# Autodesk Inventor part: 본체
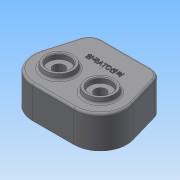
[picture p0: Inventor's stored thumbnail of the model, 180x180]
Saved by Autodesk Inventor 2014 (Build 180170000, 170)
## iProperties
Created: 2014-12
Part Number: 본체
Material: 일반
Document SubType Name: Modeling
Designer: user
Density: 1 g/cm^3
Appearance: 기본값
Author: user
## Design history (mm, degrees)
sketch "스케치1"
  geometry: L1 (-47, 36)-(47, 36); L2 (47, 36)-(62.752, -18.127); L3 (28.186, -64.186)-(-28.186, -64.186); L4 (-62.752, -18.127)-(-47, 36); L5 (-28.186, -28.186)-(0, 0); L6 (0, 0)-(28.186, -28.186); C1 r 46 at (0, 0); A1 r 36 centre (28.186, -28.186) between (28.186, -64.186) and (62.752, -18.127); A2 r 36 centre (-28.186, -28.186) between (-62.752, -18.127) and (-28.186, -64.186); 3 further points
  constraints: 12 end point, 4 point on circle, 4 tangent, 3 centre point, 2 midpoint, 2 vertical alignment, 1 coincident, 1 equal length, 1 equal radius, 1 horizontal, 1 parallel
  dimensions: "d6" = 94 distance of L1.start L1.end; "d7" = 36 radius of A2; "d10" = 36 distance from line of L1 point (0, 0); "d11" = 92 diameter of C1; "d42" = 90 deg angle of L6 L5
extrude "돌출1" new body sketch "스케치1" distance "d12" = 44; taper "d13" = 0 deg
fillet "모깎기1" dims "d14" = 18
sketch "스케치2"
  geometry: C1 r 20 at (-28.186, -28.186); C2 r 20 at (28.186, -28.186); 3 further points
  constraints: 2 centre point, 2 coincident, 1 equal radius
  dimensions: "d15" = 40 diameter of C1
extrude "돌출2" join sketch "스케치2" distance "d16" = 7; taper "d17" = -10 deg
sketch "스케치3"
  geometry: C1 r 18.766 at (0, 0) reference; C2 r 18.766 at (56.372, 0) reference; 3 further points
  constraints: 2 coincident
hole "구멍1" sketch "스케치3" at (0, 0), (56.372, 0) diameter "d18" = 30; stored, may be unused: countersink angle "d22" = 90 deg, drill point angle "d24" = 0 deg; dims "d19" = 6, "d20" = 4, "d21" = 2, "d23" = 7
sketch "스케치4"
  geometry: L1 (-50.775, 23.03)-(-62.752, -18.127) reference; L2 (-28.186, -64.186)-(28.186, -64.186) reference; L3 (62.752, -18.127)-(50.775, 23.03) reference; L4 (33.492, 36)-(-33.492, 36) reference; L5 (33.492, 31)-(-33.492, 31); L6 (-45.974, 21.633)-(-47.997, 14.681); L7 (-52.468, -0.681)-(-57.951, -19.524); L8 (57.951, -19.524)-(52.468, -0.681); L9 (47.997, 14.681)-(45.974, 21.633); L10 (-28.186, -59.186)-(-8, -59.186); L11 (8, -59.186)-(28.186, -59.186); A1 r 18 centre (-33.492, 18) between (-33.492, 36) and (-50.775, 23.03) reference; A2 r 36 centre (-28.186, -28.186) between (-62.752, -18.127) and (-28.186, -64.186) reference; A3 r 36 centre (28.186, -28.186) between (28.186, -64.186) and (62.752, -18.127) reference; A4 r 18 centre (33.492, 18) between (50.775, 23.03) and (33.492, 36) reference; A5 r 13 centre (-33.492, 18) between (-33.492, 31) and (-45.974, 21.633); A6 r 31 centre (-28.186, -28.186) between (-57.951, -19.524) and (-28.186, -59.186); A7 r 31 centre (28.186, -28.186) between (28.186, -59.186) and (57.951, -19.524); A8 r 13 centre (33.492, 18) between (45.974, 21.633) and (33.492, 31); A9 r 8 centre (-50.232, 7) between (-52.468, -0.681) and (-47.997, 14.681); A10 r 8 centre (50.232, 7) between (47.997, 14.681) and (52.468, -0.681); A11 r 8 centre (0, -59.186) between (8, -59.186) and (-8, -59.186); 1 further point
  constraints: 14 end point, 14 point on circle, 7 centre point, 2 equal radius, 1 horizontal alignment, 1 vertical alignment, 1 other
  dimensions: "d25" = 5 distance between parallel lines of L5 L4; "d27" = 8 radius of A9; "d28" = 5 radial gap between concentric circles of A1 A5; "d29" = 5 distance between parallel lines of L1 L6; "d30" = 5 distance between parallel lines of L1 L7; "d31" = 5 radial gap between concentric circles of A2 A6; "d32" = 5 distance between parallel lines of L2 L10; "d33" = 5 distance between parallel lines of L2 L11; "d34" = 5 radial gap between concentric circles of A3 A7; "d35" = 5 distance between parallel lines of L3 L8; "d36" = 5 distance from line of L3 A10.centre; "d37" = 5 distance between parallel lines of L3 L9; "d38" = 5 distance from line of L1 A9.centre; "d39" = 5 distance from line of L2 A11.centre; "d81" = 29 distance from line of A10.centre L4
extrude "돌출3" cut sketch "스케치4" distance "d40" = 34; taper "d41" = 0 deg
sketch "스케치5"
  geometry: L1 (-47.997, 14.681)-(-45.974, 21.633) reference; L2 (-57.951, -19.524)-(-52.468, -0.681) reference; L3 (-8, -59.186)-(-28.186, -59.186) reference; L4 (28.186, -59.186)-(8, -59.186) reference; L5 (52.468, -0.681)-(57.951, -19.524) reference; L6 (45.974, 21.633)-(47.997, 14.681) reference; L7 (-33.492, 31)-(33.492, 31) reference; C1 r 17.5 at (-28.186, -28.186); C2 r 17.5 at (28.186, -28.186); C3 r 20 at (0, 0); A1 r 13 centre (-33.492, 18) between (-33.492, 31) and (-45.974, 21.633) reference; A2 r 8 centre (-50.232, 7) between (-52.468, -0.681) and (-47.997, 14.681) reference; A3 r 31 centre (-28.186, -28.186) between (-57.951, -19.524) and (-28.186, -59.186) reference; A4 r 8 centre (0, -59.186) between (8, -59.186) and (-8, -59.186) reference; A5 r 31 centre (28.186, -28.186) between (28.186, -59.186) and (57.951, -19.524) reference; A6 r 8 centre (50.232, 7) between (47.997, 14.681) and (52.468, -0.681) reference; A7 r 13 centre (33.492, 18) between (45.974, 21.633) and (33.492, 31) reference; A8 r 24 centre (-28.186, -28.186) between (-23.547, -4.639) and (-4.639, -23.547); A9 r 24 centre (28.186, -28.186) between (4.639, -23.547) and (23.547, -4.639); A10 r 24 centre (0, 0) between (-4.639, -23.547) and (4.639, -23.547); A11 r 24 centre (0, 0) between (23.547, -4.639) and (-23.547, -4.639); 1 further point
  constraints: 8 point on circle, 7 centre point, 6 coincident, 4 equal radius
  dimensions: "d43" = 48 diameter of A8; "d44" = 35 diameter of C1; "d45" = 40 diameter of C3
extrude "돌출4" join sketch "스케치5" distance "d46" = 11; taper "d47" = 0 deg
sketch "스케치6"
  geometry: C1 r 10 at (0, 0); 1 further point
  constraints: 1 centre point, 1 coincident
  dimensions: "d48" = 20 diameter of C1
extrude "돌출5" cut sketch "스케치6" distance "d49" = 3; taper "d50" = 0 deg
sketch "스케치7"
  geometry: C1 r 15 at (56.372, 0) reference; C2 r 15 at (0, 0) reference; 3 further points
  constraints: 2 coincident
hole "구멍2" sketch "스케치7" at (0, 0), (56.372, 0) diameter "d51" = 15.5; stored, may be unused: countersink angle "d55" = 90 deg, drill point angle "d57" = 0 deg; dims "d52" = 6, "d53" = 4, "d54" = 2, "d56" = 10
sketch "스케치8"
  geometry: L1 (-47.997, 14.681)-(-45.974, 21.633) reference; L2 (-33.492, 31)-(33.492, 31) reference; L3 (45.974, 21.633)-(47.997, 14.681) reference; L4 (52.468, -0.681)-(57.951, -19.524) reference; L5 (28.186, -59.186)-(8, -59.186) reference; L6 (-8, -59.186)-(-28.186, -59.186) reference; L7 (-57.951, -19.524)-(-52.468, -0.681) reference; L8 (-50.775, 23.03)-(-62.752, -18.127) reference; L9 (-28.186, -64.186)-(28.186, -64.186) reference; L10 (62.752, -18.127)-(50.775, 23.03) reference; L11 (33.492, 36)-(-33.492, 36) reference; A1 r 13 centre (-33.492, 18) between (-33.492, 31) and (-45.974, 21.633) reference; A2 r 13 centre (33.492, 18) between (45.974, 21.633) and (33.492, 31) reference; A3 r 8 centre (50.232, 7) between (47.997, 14.681) and (52.468, -0.681) reference; A4 r 31 centre (28.186, -28.186) between (28.186, -59.186) and (57.951, -19.524) reference; A5 r 8 centre (0, -59.186) between (8, -59.186) and (-8, -59.186) reference; A6 r 31 centre (-28.186, -28.186) between (-57.951, -19.524) and (-28.186, -59.186) reference; A7 r 8 centre (-50.232, 7) between (-52.468, -0.681) and (-47.997, 14.681) reference; A8 r 18 centre (-33.492, 18) between (-33.492, 36) and (-50.775, 23.03) reference; A9 r 36 centre (-28.186, -28.186) between (-62.752, -18.127) and (-28.186, -64.186) reference; A10 r 36 centre (28.186, -28.186) between (28.186, -64.186) and (62.752, -18.127) reference; A11 r 18 centre (33.492, 18) between (50.775, 23.03) and (33.492, 36) reference; 4 further points
  constraints: 3 coincident
hole "구멍3" sketch "스케치8" at (-50.232, 7), (50.232, 7), (0, -59.186) diameter "d58" = 4.134; stored, may be unused: countersink angle "d62" = 90 deg, drill point angle "d64" = 118 deg; dims "d59" = 20, "d60" = 4, "d61" = 2, "d63" = 23
fillet "모깎기2" dims "d65" = 0.1
fillet "모깎기3" dims "d66" = 0.3
fillet "모깎기4" dims "d67" = 3
fillet "모깎기5" dims "d68" = 3
chamfer "모따기1" distance "d69" = 1; stored, may be unused: second distance "d70" = 2, angle "d71" = 45 deg
chamfer "모따기2" distance "d72" = 1; stored, may be unused: second distance "d73" = 2, angle "d74" = 45 deg
chamfer "모따기3" distance "d75" = 1; stored, may be unused: second distance "d76" = 2, angle "d77" = 45 deg
sketch "스케치9"
  geometry: L1 (33.492, 36)-(-33.492, 36) reference; 2 further points
  constraints: 1 vertical alignment, 1 other
  dimensions: "d78" = 30 distance from line of point (0, 6) L1
feature "엠보싱1" sketch "스케치9" dims "d79" = 1, "d80" = 0
sketch "스케치10"
  geometry: 1 further point
chamfer "모따기4" distance "d82" = 1; stored, may be unused: second distance "d83" = 2, angle "d84" = 45 deg
chamfer "모따기5" distance "d85" = 1; stored, may be unused: second distance "d86" = 2, angle "d87" = 45 deg
node "솔리드1"
node "투영된 루프1"
node "투영된 루프2"
node "투영된 루프3"
node "투영된 루프4"
node "투영된 루프5"
node "투영된 루프6"
node "투영된 루프7"
